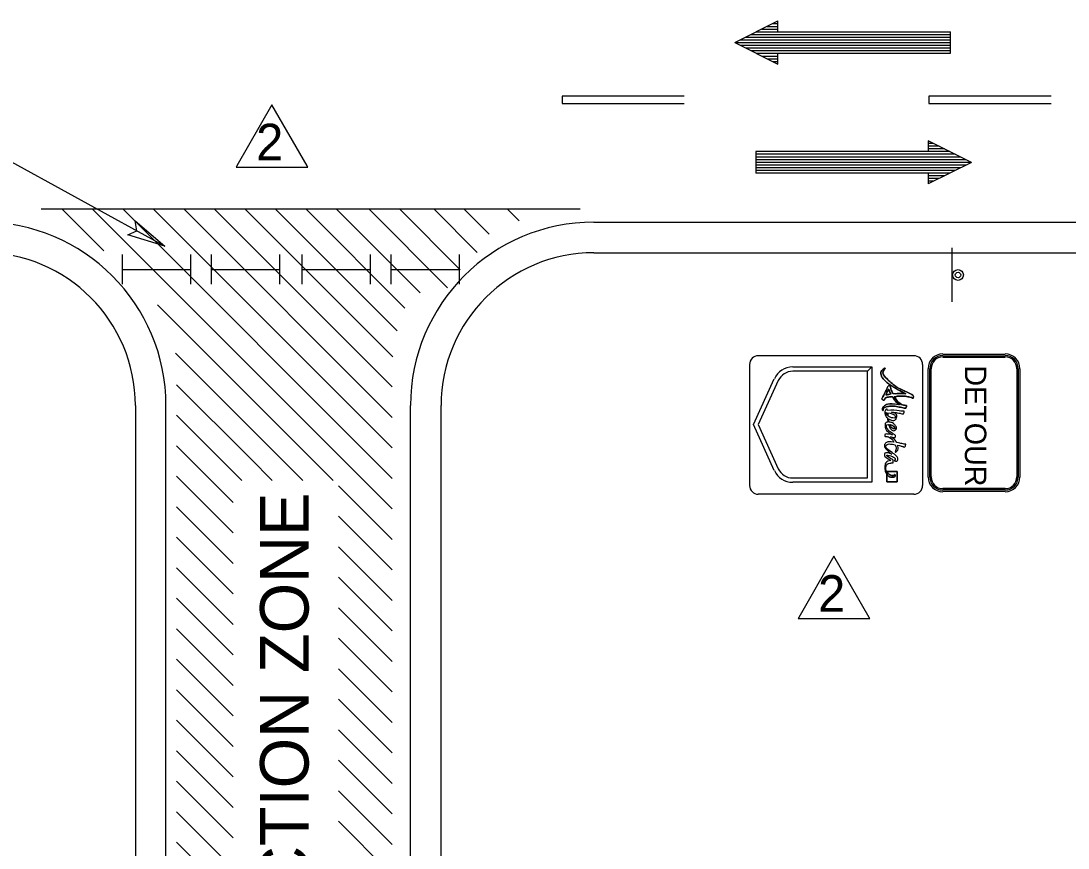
# Model space of a CAD drawing. Extents: x 1806 to 2022, y 110 to 389.
# Drawn here: x 1873.19 to 1914.62, y 254.59 to 287.32 of the extents above; entities that cross this region are included whole.
import ezdxf

# ---------------------------------------------------------------- set-up
doc = ezdxf.new("R2010")
doc.units = 0
for name, color, linetype in [('Level 10', 7, 'Continuous'), ('Level 2', 7, 'Continuous'), ('Level 44', 7, 'Continuous'), ('Level 50', 7, 'Continuous'), ('Level 53', 7, 'Continuous'), ('Level 60', 7, 'Continuous')]:
    doc.layers.add(name, color=color, linetype=linetype)

msp = doc.modelspace()

# ---------------------------------------------------------------- linework, layer by layer
at = {"layer": 'Level 10'}
for p, q in [((1871.758, 282.31), (1878.875, 278.409)), ((1873.98, 279.878), (1895.312, 279.878)), ((1874.804, 279.878), (1876.462, 278.22)), ((1876.01, 279.878), (1887.876, 268.013)), ((1877.216, 279.878), (1887.876, 269.219)), ((1878.423, 279.878), (1887.876, 270.426)), ((1879.63, 279.878), (1887.876, 271.633)), ((1880.837, 279.878), (1887.876, 272.84)), ((1882.044, 279.878), (1887.899, 274.023)), ((1883.25, 279.878), (1888.073, 275.056)), ((1884.457, 279.878), (1888.376, 275.959)), ((1885.663, 279.878), (1888.979, 276.562)), ((1886.951, 279.878), (1890.069, 276.76)), ((1888.159, 279.878), (1890.563, 277.474)), ((1889.52, 279.878), (1891.244, 278.154)), ((1890.708, 279.878), (1891.712, 278.874)), ((1892.421, 279.878), (1892.895, 279.404)), ((1895.86, 279.357), (1957.331, 279.357)), ((1877.203, 276.903), (1877.203, 278.082)), ((1879.903, 276.903), (1879.903, 278.082)), ((1880.726, 276.903), (1880.726, 278.082)), ((1883.426, 276.903), (1883.426, 278.082)), ((1884.314, 276.903), (1884.314, 278.082)), ((1887.014, 276.903), (1887.014, 278.082)), ((1887.837, 276.903), (1887.837, 278.082)), ((1890.537, 276.903), (1890.537, 278.082)), ((1895.86, 278.148), (1957.331, 278.148)), ((1877.203, 277.489), (1879.903, 277.489)), ((1880.726, 277.489), (1883.426, 277.489)), ((1884.314, 277.489), (1887.014, 277.489)), ((1887.837, 277.489), (1890.537, 277.489)), ((1878.592, 276.09), (1884.304, 270.378)), ((1879.305, 274.169), (1883.097, 270.378)), ((1879.343, 272.925), (1882.264, 270.004)), ((1877.715, 272.1), (1877.715, 233.074)), ((1878.925, 233.074), (1878.925, 272.1)), ((1888.603, 233.074), (1888.603, 272.1)), ((1889.812, 233.074), (1889.812, 272.1)), ((1879.343, 271.719), (1881.92, 269.141)), ((1879.343, 270.512), (1881.587, 268.268)), ((1883.097, 270.378), (1884.334, 269.141)), ((1884.304, 270.378), (1885.541, 269.141)), ((1882.264, 270.004), (1883.127, 269.141)), ((1881.661, 269.401), (1881.921, 269.141)), ((1879.343, 269.306), (1881.587, 267.062)), ((1885.752, 268.93), (1887.876, 266.806)), ((1879.343, 268.098), (1881.587, 265.854)), ((1885.752, 267.723), (1887.876, 265.599)), ((1879.343, 266.892), (1881.587, 264.647)), ((1885.752, 266.516), (1887.876, 264.392)), ((1879.343, 265.685), (1881.587, 263.441)), ((1885.752, 265.31), (1887.876, 263.186)), ((1879.343, 264.478), (1881.587, 262.234)), ((1885.752, 264.103), (1887.876, 261.979)), ((1879.343, 263.271), (1881.587, 261.027)), ((1885.752, 262.896), (1887.876, 260.772)), ((1879.343, 262.064), (1881.587, 259.82)), ((1885.752, 261.689), (1887.876, 259.565)), ((1879.343, 260.858), (1881.587, 258.613)), ((1885.752, 260.482), (1887.876, 258.358)), ((1879.343, 259.651), (1881.587, 257.407)), ((1885.752, 259.276), (1887.876, 257.152)), ((1879.343, 258.445), (1881.587, 256.2)), ((1885.752, 258.069), (1887.876, 255.945)), ((1879.343, 257.237), (1881.587, 254.993)), ((1885.752, 256.862), (1887.876, 254.738)), ((1879.343, 256.031), (1881.587, 253.786)), ((1885.752, 255.655), (1887.876, 253.531)), ((1879.343, 254.824), (1881.587, 252.58))]:
    msp.add_line(p, q, dxfattribs=at)
msp.add_lwpolyline([(1878.875, 278.409), (1877.411, 278.858), (1877.777, 279.011), (1877.709, 279.402)], close=True, dxfattribs=at)
for centre, radius, start, end in [((1871.667, 272.1), 7.258, 0, 90), ((1895.86, 272.1), 7.258, 90, 180), ((1871.667, 272.1), 6.048, 0, 90), ((1895.86, 272.1), 6.048, 90, 180)]:
    msp.add_arc(centre, radius, start, end, dxfattribs=at)
at = {"layer": 'Level 2'}
for p, q in [((1899.435, 284.342), (1894.597, 284.342)), ((1894.597, 284.342), (1894.597, 284.052)), ((1913.949, 284.342), (1909.111, 284.342)), ((1909.111, 284.342), (1909.111, 284.052)), ((1894.597, 284.052), (1899.435, 284.052)), ((1909.111, 284.052), (1913.949, 284.052)), ((1908.517, 274.071), (1902.363, 274.071)), ((1902.016, 273.724), (1902.016, 268.939)), ((1903.725, 273.628), (1906.852, 273.628)), ((1906.852, 273.628), (1906.681, 273.457)), ((1906.681, 273.457), (1906.852, 273.628)), ((1906.852, 273.628), (1906.852, 269.063)), ((1908.864, 273.724), (1908.864, 268.939)), ((1908.864, 273.724), (1908.864, 268.939)), ((1902.172, 271.345), (1902.997, 273.16)), ((1903.153, 273.089), (1902.36, 271.345)), ((1906.681, 273.457), (1903.725, 273.457)), ((1906.681, 269.234), (1906.681, 273.457)), ((1902.997, 269.531), (1902.172, 271.345)), ((1902.36, 271.345), (1903.153, 269.602)), ((1903.725, 269.234), (1906.681, 269.234)), ((1906.852, 269.063), (1903.725, 269.063)), ((1908.517, 268.592), (1902.363, 268.592))]:
    msp.add_line(p, q, dxfattribs=at)
for centre, radius, start, end in [((1902.363, 273.724), 0.347, 90, 180), ((1908.517, 273.724), 0.347, 360, 90), ((1903.725, 272.829), 0.799, 90, 155.5432), ((1903.725, 272.829), 0.628, 90, 155.5432), ((1903.725, 269.862), 0.799, 204.4568, 270), ((1903.725, 269.862), 0.628, 204.4568, 270), ((1902.363, 268.939), 0.347, 180, 270), ((1908.517, 268.939), 0.347, 270, 360)]:
    msp.add_arc(centre, radius, start, end, dxfattribs=at)
at = {"layer": 'Level 44'}
for p, q in [((1910.027, 278.336), (1910.027, 276.203)), ((1909.666, 274.02), (1912.131, 274.02)), ((1909.667, 274.134), (1912.132, 274.134)), ((1909.667, 274.069), (1912.132, 274.069)), ((1909.667, 274.015), (1912.132, 274.015)), ((1909.667, 274.015), (1912.132, 274.015)), ((1909.085, 269.268), (1909.085, 273.559)), ((1909.15, 269.268), (1909.15, 273.559)), ((1909.203, 269.273), (1909.203, 273.564)), ((1909.204, 269.268), (1909.204, 273.559)), ((1909.204, 269.268), (1909.204, 273.559)), ((1912.587, 273.564), (1912.587, 269.273)), ((1912.588, 273.559), (1912.588, 269.268)), ((1912.588, 273.559), (1912.588, 269.268)), ((1912.642, 273.559), (1912.642, 269.268)), ((1912.707, 273.559), (1912.707, 269.268)), ((1909.197, 271.198), (1909.197, 271.198)), ((1909.198, 271.193), (1909.198, 271.193)), ((1909.198, 271.193), (1909.198, 271.193)), ((1909.308, 269.325), (1909.31, 269.321)), ((1909.202, 269.272), (1909.204, 269.268)), ((1909.25, 269.296), (1909.252, 269.292)), ((1912.131, 268.821), (1909.666, 268.821)), ((1912.132, 268.816), (1909.667, 268.816)), ((1912.132, 268.816), (1909.667, 268.816)), ((1912.132, 268.762), (1909.667, 268.762)), ((1912.132, 268.697), (1909.667, 268.697))]:
    msp.add_line(p, q, dxfattribs=at)
for radius in [0.213, 0.107]:
    msp.add_circle((1910.266, 277.266), radius, dxfattribs=at)
for centre, radius, start, end in [((1909.663, 273.559), 0.581, 90, 180), ((1909.663, 273.559), 0.516, 90, 180), ((1909.662, 273.564), 0.462, 90, 180), ((1909.663, 273.559), 0.462, 90, 180), ((1909.663, 273.559), 0.462, 90, 180), ((1912.132, 273.564), 0.462, 0, 90), ((1912.133, 273.559), 0.581, 0, 90), ((1912.133, 273.559), 0.516, 0, 90), ((1912.133, 273.559), 0.462, 0, 90), ((1912.133, 273.559), 0.462, 0, 90), ((1909.663, 269.272), 0.581, 180, 270), ((1909.663, 269.272), 0.516, 180, 270), ((1909.662, 269.277), 0.462, 180, 270), ((1909.663, 269.272), 0.462, 180, 270), ((1909.663, 269.272), 0.462, 180, 270), ((1912.132, 269.277), 0.462, 270, 360), ((1912.133, 269.272), 0.462, 270, 360), ((1912.133, 269.272), 0.581, 270, 360), ((1912.133, 269.272), 0.516, 270, 360), ((1912.133, 269.272), 0.462, 270, 360)]:
    msp.add_arc(centre, radius, start, end, dxfattribs=at)
at = {"layer": 'Level 50'}
for p, q in [((1901.432, 286.462), (1903.139, 287.316)), ((1902.926, 287.209), (1903.139, 287.209)), ((1903.139, 286.889), (1903.139, 287.316)), ((1902.072, 286.782), (1909.966, 286.782)), ((1902.286, 286.889), (1909.966, 286.889)), ((1902.499, 286.996), (1903.139, 286.996)), ((1902.712, 287.102), (1903.139, 287.102)), ((1903.139, 286.889), (1909.966, 286.889)), ((1909.966, 286.036), (1909.966, 286.889)), ((1901.432, 286.462), (1909.966, 286.462)), ((1901.432, 286.462), (1903.139, 285.609)), ((1901.646, 286.569), (1909.966, 286.569)), ((1901.646, 286.356), (1909.966, 286.356)), ((1901.859, 286.676), (1909.966, 286.676)), ((1901.859, 286.249), (1909.966, 286.249)), ((1902.072, 286.142), (1909.966, 286.142)), ((1902.286, 286.036), (1909.966, 286.036)), ((1902.499, 285.929), (1903.139, 285.929)), ((1903.139, 286.036), (1909.966, 286.036)), ((1903.139, 285.609), (1903.139, 286.036)), ((1902.712, 285.822), (1903.139, 285.822)), ((1902.926, 285.716), (1903.139, 285.716)), ((1910.795, 281.719), (1909.088, 282.573)), ((1909.088, 282.573), (1909.088, 282.146)), ((1909.302, 282.466), (1909.088, 282.466)), ((1909.515, 282.359), (1909.088, 282.359)), ((1909.728, 282.253), (1909.088, 282.253)), ((1909.088, 282.146), (1902.262, 282.146)), ((1902.262, 282.146), (1902.262, 281.293)), ((1909.942, 282.146), (1902.262, 282.146)), ((1910.155, 282.039), (1902.262, 282.039)), ((1910.368, 281.933), (1902.262, 281.933)), ((1910.582, 281.826), (1902.262, 281.826)), ((1910.795, 281.719), (1902.262, 281.719)), ((1910.582, 281.613), (1902.262, 281.613)), ((1910.368, 281.506), (1902.262, 281.506)), ((1910.155, 281.399), (1902.262, 281.399)), ((1910.795, 281.719), (1909.088, 280.866)), ((1909.088, 281.293), (1902.262, 281.293)), ((1909.942, 281.293), (1902.262, 281.293)), ((1909.088, 281.293), (1909.088, 280.866)), ((1909.728, 281.186), (1909.088, 281.186)), ((1909.515, 281.079), (1909.088, 281.079)), ((1909.302, 280.973), (1909.088, 280.973))]:
    msp.add_line(p, q, dxfattribs=at)
at = {"layer": 'Level 53'}
msp.add_line((1907.447, 269.383), (1907.447, 269.483), dxfattribs=at)
msp.add_lwpolyline([(1907.447, 269.383), (1907.447, 269.088), (1907.855, 269.088), (1907.855, 269.495), (1907.447, 269.495), (1907.447, 269.483)], dxfattribs=at)
for points, degree in [([(1907.3, 271.937), (1907.306, 271.98), (1907.366, 272.038), (1907.464, 272.055), (1907.64, 272.087), (1907.814, 272.068), (1908.074, 272.016), (1908.123, 272.006), (1908.208, 271.973), (1908.224, 272.079), (1908.23, 272.113), (1908.213, 272.096), (1908.168, 272.105), (1907.975, 272.146), (1907.836, 272.304), (1907.742, 272.463), (1907.963, 272.48), (1908.209, 272.473), (1908.36, 272.431), (1908.487, 272.396), (1908.464, 272.354), (1908.49, 272.406), (1908.519, 272.461), (1908.481, 272.519), (1908.387, 272.567), (1908.292, 272.614), (1907.778, 272.833), (1907.431, 273.182), (1907.253, 273.36), (1907.344, 273.522), (1907.372, 273.554), (1907.394, 273.581), (1907.36, 273.59), (1907.324, 273.558), (1907.169, 273.413), (1907.258, 273.202), (1907.335, 273.125), (1907.547, 272.913), (1908.004, 272.666), (1908.198, 272.566), (1908.089, 272.575), (1907.906, 272.578), (1907.691, 272.558), (1907.639, 272.666), (1907.608, 272.763), (1907.596, 272.809), (1907.583, 272.858), (1907.562, 272.889), (1907.539, 272.89), (1907.514, 272.891), (1907.493, 272.858), (1907.47, 272.81), (1907.43, 272.724), (1907.311, 272.473), (1907.276, 272.412), (1907.245, 272.359), (1907.269, 272.333), (1907.302, 272.317), (1907.345, 272.297), (1907.37, 272.353), (1907.386, 272.407), (1907.459, 272.428), (1907.557, 272.445), (1907.664, 272.456), (1907.743, 272.329), (1907.847, 272.203), (1907.978, 272.131), (1907.869, 272.149), (1907.498, 272.196), (1907.341, 272.079), (1907.306, 272.053), (1907.269, 271.996), (1907.274, 271.941), (1907.277, 271.914), (1907.294, 271.901), (1907.299, 271.904), (1907.305, 271.906), (1907.297, 271.921), (1907.3, 271.937)], 3), ([(1907.742, 272.463), (1907.963, 272.48), (1908.209, 272.473), (1908.36, 272.431), (1908.487, 272.396), (1908.464, 272.354), (1908.49, 272.406), (1908.519, 272.461), (1908.481, 272.519), (1908.387, 272.567), (1908.292, 272.614), (1907.778, 272.833), (1907.431, 273.182), (1907.253, 273.36), (1907.344, 273.522), (1907.372, 273.554), (1907.394, 273.581), (1907.36, 273.59), (1907.324, 273.558), (1907.169, 273.413), (1907.258, 273.202), (1907.335, 273.125), (1907.547, 272.913), (1908.004, 272.666), (1908.198, 272.566)], 3), ([(1907.691, 272.558), (1907.639, 272.666), (1907.608, 272.763), (1907.596, 272.809), (1907.583, 272.858), (1907.562, 272.889), (1907.539, 272.89), (1907.514, 272.891), (1907.493, 272.858), (1907.47, 272.81), (1907.43, 272.724), (1907.311, 272.473), (1907.276, 272.412), (1907.245, 272.359), (1907.269, 272.333), (1907.302, 272.317), (1907.345, 272.297), (1907.37, 272.353), (1907.386, 272.407)], 3), ([(1907.416, 272.516), (1907.436, 272.571), (1907.468, 272.65), (1907.521, 272.754)], 2), ([(1907.521, 272.754), (1907.542, 272.697), (1907.572, 272.625), (1907.611, 272.55), (1907.525, 272.539), (1907.462, 272.528), (1907.416, 272.516), (1907.436, 272.571), (1907.468, 272.65), (1907.521, 272.754)], 3), ([(1907.521, 272.754), (1907.542, 272.697), (1907.572, 272.625), (1907.611, 272.55)], 2), ([(1907.3, 271.937), (1907.306, 271.98), (1907.366, 272.038), (1907.464, 272.055), (1907.64, 272.087), (1907.814, 272.068), (1908.074, 272.016), (1908.123, 272.006), (1908.208, 271.973), (1908.224, 272.079), (1908.23, 272.113), (1908.213, 272.096), (1908.168, 272.105), (1907.975, 272.146), (1907.836, 272.304), (1907.742, 272.463)], 3), ([(1907.386, 272.407), (1907.459, 272.428), (1907.557, 272.445), (1907.664, 272.456)], 2), ([(1907.611, 272.55), (1907.525, 272.539), (1907.462, 272.528), (1907.416, 272.516)], 2), ([(1907.664, 272.456), (1907.743, 272.329), (1907.847, 272.203), (1907.978, 272.131)], 2), ([(1908.198, 272.566), (1908.089, 272.575), (1907.906, 272.578), (1907.691, 272.558)], 2), ([(1907.978, 272.131), (1907.869, 272.149), (1907.498, 272.196), (1907.341, 272.079), (1907.306, 272.053), (1907.269, 271.996), (1907.274, 271.941), (1907.277, 271.914), (1907.294, 271.901), (1907.299, 271.904), (1907.305, 271.906), (1907.297, 271.921), (1907.3, 271.937)], 3), ([(1907.48, 271.908), (1907.465, 271.954), (1907.431, 271.973), (1907.394, 271.914), (1907.369, 271.873), (1907.361, 271.783), (1907.406, 271.693), (1907.422, 271.661), (1907.444, 271.633), (1907.47, 271.609)], 3), ([(1907.413, 271.788), (1907.411, 271.803), (1907.411, 271.815), (1907.413, 271.825)], 2), ([(1907.413, 271.825), (1907.418, 271.819), (1907.425, 271.816), (1907.434, 271.816), (1907.439, 271.816), (1907.445, 271.815), (1907.451, 271.815)], 3), ([(1907.451, 271.815), (1907.452, 271.792), (1907.455, 271.756), (1907.459, 271.713)], 2), ([(1907.636, 271.839), (1907.74, 271.83), (1907.866, 271.814), (1907.984, 271.79), (1908.033, 271.78), (1908.118, 271.747), (1908.134, 271.853), (1908.139, 271.887), (1908.124, 271.882), (1908.078, 271.879), (1908.016, 271.876), (1907.644, 271.944), (1907.48, 271.908)], 3), ([(1907.503, 271.681), (1907.499, 271.722), (1907.495, 271.765), (1907.491, 271.811)], 2), ([(1907.491, 271.811), (1907.622, 271.794), (1907.804, 271.726), (1907.775, 271.641), (1907.758, 271.592), (1907.605, 271.618), (1907.503, 271.681)], 3), ([(1907.515, 271.576), (1907.638, 271.5), (1907.804, 271.507), (1907.832, 271.618), (1907.865, 271.746), (1907.74, 271.811), (1907.636, 271.839)], 3), ([(1907.496, 271.447), (1907.425, 271.438), (1907.37, 271.391), (1907.38, 271.283), (1907.394, 271.128), (1907.584, 270.991), (1907.675, 270.939)], 3), ([(1907.459, 271.713), (1907.434, 271.736), (1907.417, 271.761), (1907.413, 271.788)], 2), ([(1907.47, 271.609), (1907.477, 271.555), (1907.486, 271.499), (1907.496, 271.447)], 2), ([(1907.537, 271.448), (1907.529, 271.486), (1907.522, 271.528), (1907.515, 271.576)], 2), ([(1907.519, 271.352), (1907.525, 271.335), (1907.53, 271.319), (1907.536, 271.306), (1907.608, 271.144), (1907.715, 271.089), (1907.781, 271.13), (1907.843, 271.169), (1907.824, 271.28), (1907.732, 271.368), (1907.686, 271.411), (1907.608, 271.444), (1907.537, 271.448)], 3), ([(1907.675, 270.939), (1907.577, 270.948), (1907.363, 271.012), (1907.374, 270.903), (1907.379, 270.861), (1907.385, 270.879), (1907.422, 270.877), (1907.551, 270.867), (1907.661, 270.76), (1907.728, 270.654)], 3), ([(1907.595, 270.864), (1907.645, 270.854), (1907.701, 270.838), (1907.739, 270.837), (1907.779, 270.835), (1907.788, 270.863), (1907.791, 270.873), (1907.797, 270.896), (1907.786, 270.924), (1907.747, 270.952), (1907.656, 271.016), (1907.512, 271.098), (1907.452, 271.222), (1907.409, 271.311), (1907.452, 271.35), (1907.519, 271.352)], 3), ([(1907.724, 271.266), (1907.774, 271.212), (1907.77, 271.185), (1907.757, 271.178), (1907.728, 271.163), (1907.625, 271.226), (1907.569, 271.348)], 3), ([(1907.569, 271.348), (1907.624, 271.338), (1907.684, 271.309), (1907.724, 271.266)], 2), ([(1907.728, 270.654), (1907.57, 270.672), (1907.429, 270.666), (1907.384, 270.594), (1907.301, 270.462), (1907.518, 270.275), (1907.651, 270.173)], 3), ([(1907.411, 269.609), (1907.411, 269.776), (1907.541, 269.819), (1907.605, 269.827), (1907.648, 269.833), (1907.71, 269.824), (1907.702, 269.897), (1907.696, 269.949), (1907.595, 269.996), (1907.511, 270.061), (1907.438, 270.118), (1907.445, 270.143), (1907.507, 270.13), (1907.586, 270.113), (1907.769, 270.048), (1907.783, 269.973), (1907.789, 269.939), (1907.728, 269.927), (1907.766, 269.911), (1907.804, 269.895), (1907.886, 269.909), (1907.886, 269.987), (1907.886, 270.041), (1907.829, 270.106), (1907.763, 270.159), (1907.706, 270.205), (1907.361, 270.44), (1907.436, 270.539), (1907.47, 270.585), (1907.612, 270.581), (1907.78, 270.552)], 3), ([(1907.838, 270.638), (1907.788, 270.724), (1907.704, 270.805), (1907.595, 270.864)], 2), ([(1907.881, 270.532), (1907.935, 270.52), (1907.99, 270.507), (1908.044, 270.492), (1908.093, 270.478), (1908.178, 270.437), (1908.194, 270.543), (1908.2, 270.576), (1908.183, 270.562), (1908.138, 270.573), (1908.055, 270.593), (1907.946, 270.619), (1907.838, 270.638)], 3), ([(1907.651, 270.173), (1907.533, 270.225), (1907.382, 270.255), (1907.359, 270.176), (1907.332, 270.084), (1907.485, 270.011), (1907.602, 269.926)], 3), ([(1907.78, 270.552), (1907.825, 270.435), (1907.81, 270.338), (1907.784, 270.283), (1907.771, 270.256), (1907.772, 270.252), (1907.802, 270.264), (1907.846, 270.281), (1907.915, 270.375), (1907.883, 270.522), (1907.882, 270.525), (1907.882, 270.529), (1907.881, 270.532)], 3), ([(1907.602, 269.926), (1907.518, 269.916), (1907.373, 269.86), (1907.373, 269.634), (1907.373, 269.533), (1907.402, 269.447), (1907.447, 269.383)], 3), ([(1907.447, 269.483), (1907.425, 269.521), (1907.411, 269.563), (1907.411, 269.609)], 2), ([(1907.855, 269.495), (1907.855, 269.495), (1907.447, 269.495), (1907.447, 269.495), (1907.447, 269.495), (1907.447, 269.483), (1907.447, 269.483), (1907.5, 269.395), (1907.601, 269.335), (1907.685, 269.335), (1907.757, 269.335), (1907.753, 269.374), (1907.763, 269.369), (1907.792, 269.357), (1907.775, 269.267), (1907.674, 269.262), (1907.588, 269.257), (1907.504, 269.302), (1907.447, 269.383), (1907.447, 269.383), (1907.447, 269.088), (1907.447, 269.088), (1907.447, 269.088), (1907.855, 269.088), (1907.855, 269.088), (1907.855, 269.088), (1907.855, 269.495), (1907.855, 269.495)], 3), ([(1907.447, 269.483), (1907.5, 269.395), (1907.601, 269.335), (1907.685, 269.335), (1907.757, 269.335), (1907.753, 269.374), (1907.763, 269.369), (1907.792, 269.357), (1907.775, 269.267), (1907.674, 269.262), (1907.588, 269.257), (1907.504, 269.302), (1907.447, 269.383)], 3)]:
    msp.add_open_spline(points, degree=degree, dxfattribs=at)
at = {"layer": 'Level 60'}
for points in [[(1883.117, 284.003), (1881.724, 281.578)], [(1884.511, 281.578), (1883.117, 284.003)], [(1881.724, 281.578), (1881.698, 281.533), (1884.537, 281.533), (1884.511, 281.578)], [(1905.355, 266.141), (1903.962, 263.716)], [(1906.749, 263.716), (1905.355, 266.141)], [(1903.962, 263.716), (1903.936, 263.671), (1906.775, 263.671), (1906.749, 263.716)]]:
    msp.add_lwpolyline(points, dxfattribs=at)

# ---------------------------------------------------------------- texts
at = {"layer": 'Level 44'}
msp.add_text('DETOUR', height=0.848, rotation=270, dxfattribs=at).set_placement((1910.538, 273.688))
at = {"layer": 'Level 50'}
msp.add_text('CONSTRUCTION ZONE', height=1.92, rotation=90, dxfattribs=at).set_placement((1884.568, 240.126))
at = {"layer": 'Level 60'}
for p in [(1882.49, 281.802), (1904.728, 263.94)]:
    msp.add_text('2', height=1.448, rotation=360, dxfattribs=at).set_placement(p)

doc.saveas('drawing.dxf')
